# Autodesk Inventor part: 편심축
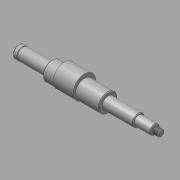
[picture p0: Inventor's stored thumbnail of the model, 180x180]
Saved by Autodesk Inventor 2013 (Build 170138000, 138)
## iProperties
Created: 2015-09
Part Number: 편심축
Material: 강철, 연강
Document SubType Name: Modeling
Designer: mduedu
Density: 1 g/cm^3
Author: mduedu
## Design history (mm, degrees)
sketch "스케치1"
  geometry: L1 (-88.5, 0)-(88.5, 0); L2 (-88.5, 0)-(-88.5, 7.5); L3 (-88.5, 7.5)-(-47.35, 7.5); L4 (-47.35, 7.5)-(-47.35, 11.5); L5 (-47.35, 11.5)-(22.65, 11.5); L6 (22.65, 11.5)-(22.65, 7.5); L7 (22.65, 7.5)-(60.65, 7.5); L8 (60.65, 7.5)-(60.65, 6); L9 (60.65, 6)-(80.65, 6); L10 (80.65, 6)-(80.65, 3); L11 (80.65, 3)-(81.65, 3); L12 (81.65, 3)-(81.65, 4); L13 (81.65, 4)-(88.5, 4); L14 (88.5, 4)-(88.5, 0); 2 further points
  constraints: 28 end point, 10 parallel, 2 perpendicular, 1 coincident, 1 collinear, 1 horizontal, 1 midpoint
  dimensions: "d0" = 41.15 distance of L2.end L3.end; "d2" = 70 distance of L4.end L5.end; "d3" = 38 distance of L6.end L7.end; "d4" = 177 distance of L1.start L1.end; "d5" = 20 distance of L8.end L9.end; "d6" = 1 distance of L10.end L11.end; "d7" = 8 diameter of L13 L1; "d8" = 6 diameter of L11 L1; "d9" = 12 diameter of L9 L1; "d10" = 15 diameter of L7 L1; "d11" = 23 diameter of L5 L1; "d12" = 15 diameter of L3 L1
revolve "회전1" sketch "스케치1" stored, may be unused: angle "d13" = 90 deg
sketch "스케치2"
  geometry: L1 (-88.5, 7.5)-(-47.35, 7.5) reference; L2 (-88.5, -7.5)-(-88.5, 7.5) reference; L3 (88.5, -4)-(88.5, 4) reference; L4 (-88.5, 0)-(88.5, 0); L5 (-83.5, 7.5)-(-82.35, 7.5); L6 (-82.35, 7.5)-(-82.35, 7.15); L7 (-82.35, 7.15)-(-83.5, 7.15); L8 (-83.5, 7.15)-(-83.5, 7.5); 1 further point
  constraints: 10 end point, 2 midpoint, 2 parallel, 1 horizontal, 1 perpendicular, 1 point on line
  dimensions: "d14" = 5 distance between parallel lines of L8 L2; "d15" = 14.3 diameter of L7 L4; "d16" = 1.15 distance of L6.end L7.end
revolve "회전2" sketch "스케치2" stored, may be unused: angle "d17" = 90 deg
node "작업 평면1"
sketch "스케치3"
  geometry: C1 r 11.5 at (0, 0) reference; C2 r 14 at (0, 2.5); 1 further point
  constraints: 1 centre point, 1 tangent, 1 vertical alignment
  dimensions: "d19" = 28 diameter of C2
extrude "돌출1" join sketch "스케치3" distance "d21" = 25; taper "d22" = 0 deg
node "작업 평면2"
sketch "스케치4"
  geometry: L1 (10, 7.5)-(10, -7.5) reference; L2 (-10, 6)-(-10, -6) reference; L3 (10, 0)-(-10, 0); L4 (-5, -2)-(3, -2); L5 (3, 2)-(-5, 2); A1 r 2 centre (3, 0) between (3, -2) and (3, 2); A2 r 2 centre (-5, 0) between (-5, 2) and (-5, -2); 1 further point
  constraints: 6 end point, 4 point on circle, 4 tangent, 2 centre point, 2 midpoint, 2 parallel, 1 point on line
  dimensions: "d23" = 4 distance between parallel lines of L5 L4; "d25" = 12 dimension on A2 A1; "d26" = 3 distance edge to line of A2 L2
extrude "돌출2" cut sketch "스케치4" distance "d27" = 2.5; taper "d28" = 0 deg
chamfer "모따기1" distance "d29" = 1; stored, may be unused: second distance "d30" = 2, angle "d31" = 45 deg
feature "스레드1" dims "d32" = 10, "d33" = 0
chamfer "모따기2" distance "d34" = 1; stored, may be unused: second distance "d35" = 2, angle "d36" = 45 deg
chamfer "모따기3" distance "d37" = 1; stored, may be unused: second distance "d38" = 2, angle "d39" = 45 deg
sketch "스케치5"
  geometry: 1 further point
node "솔리드1"
other parameters: "d18" = -29.5
